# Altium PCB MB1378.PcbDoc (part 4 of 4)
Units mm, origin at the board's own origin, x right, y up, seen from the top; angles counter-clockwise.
Board outline 54.22 x 80.1 mm, 4 copper layers (Top Layer, L2-GND, L3, Bottom Layer), stack 0.771 mm thick; 206 components, 159 nets, 727 pads, 330 vias.
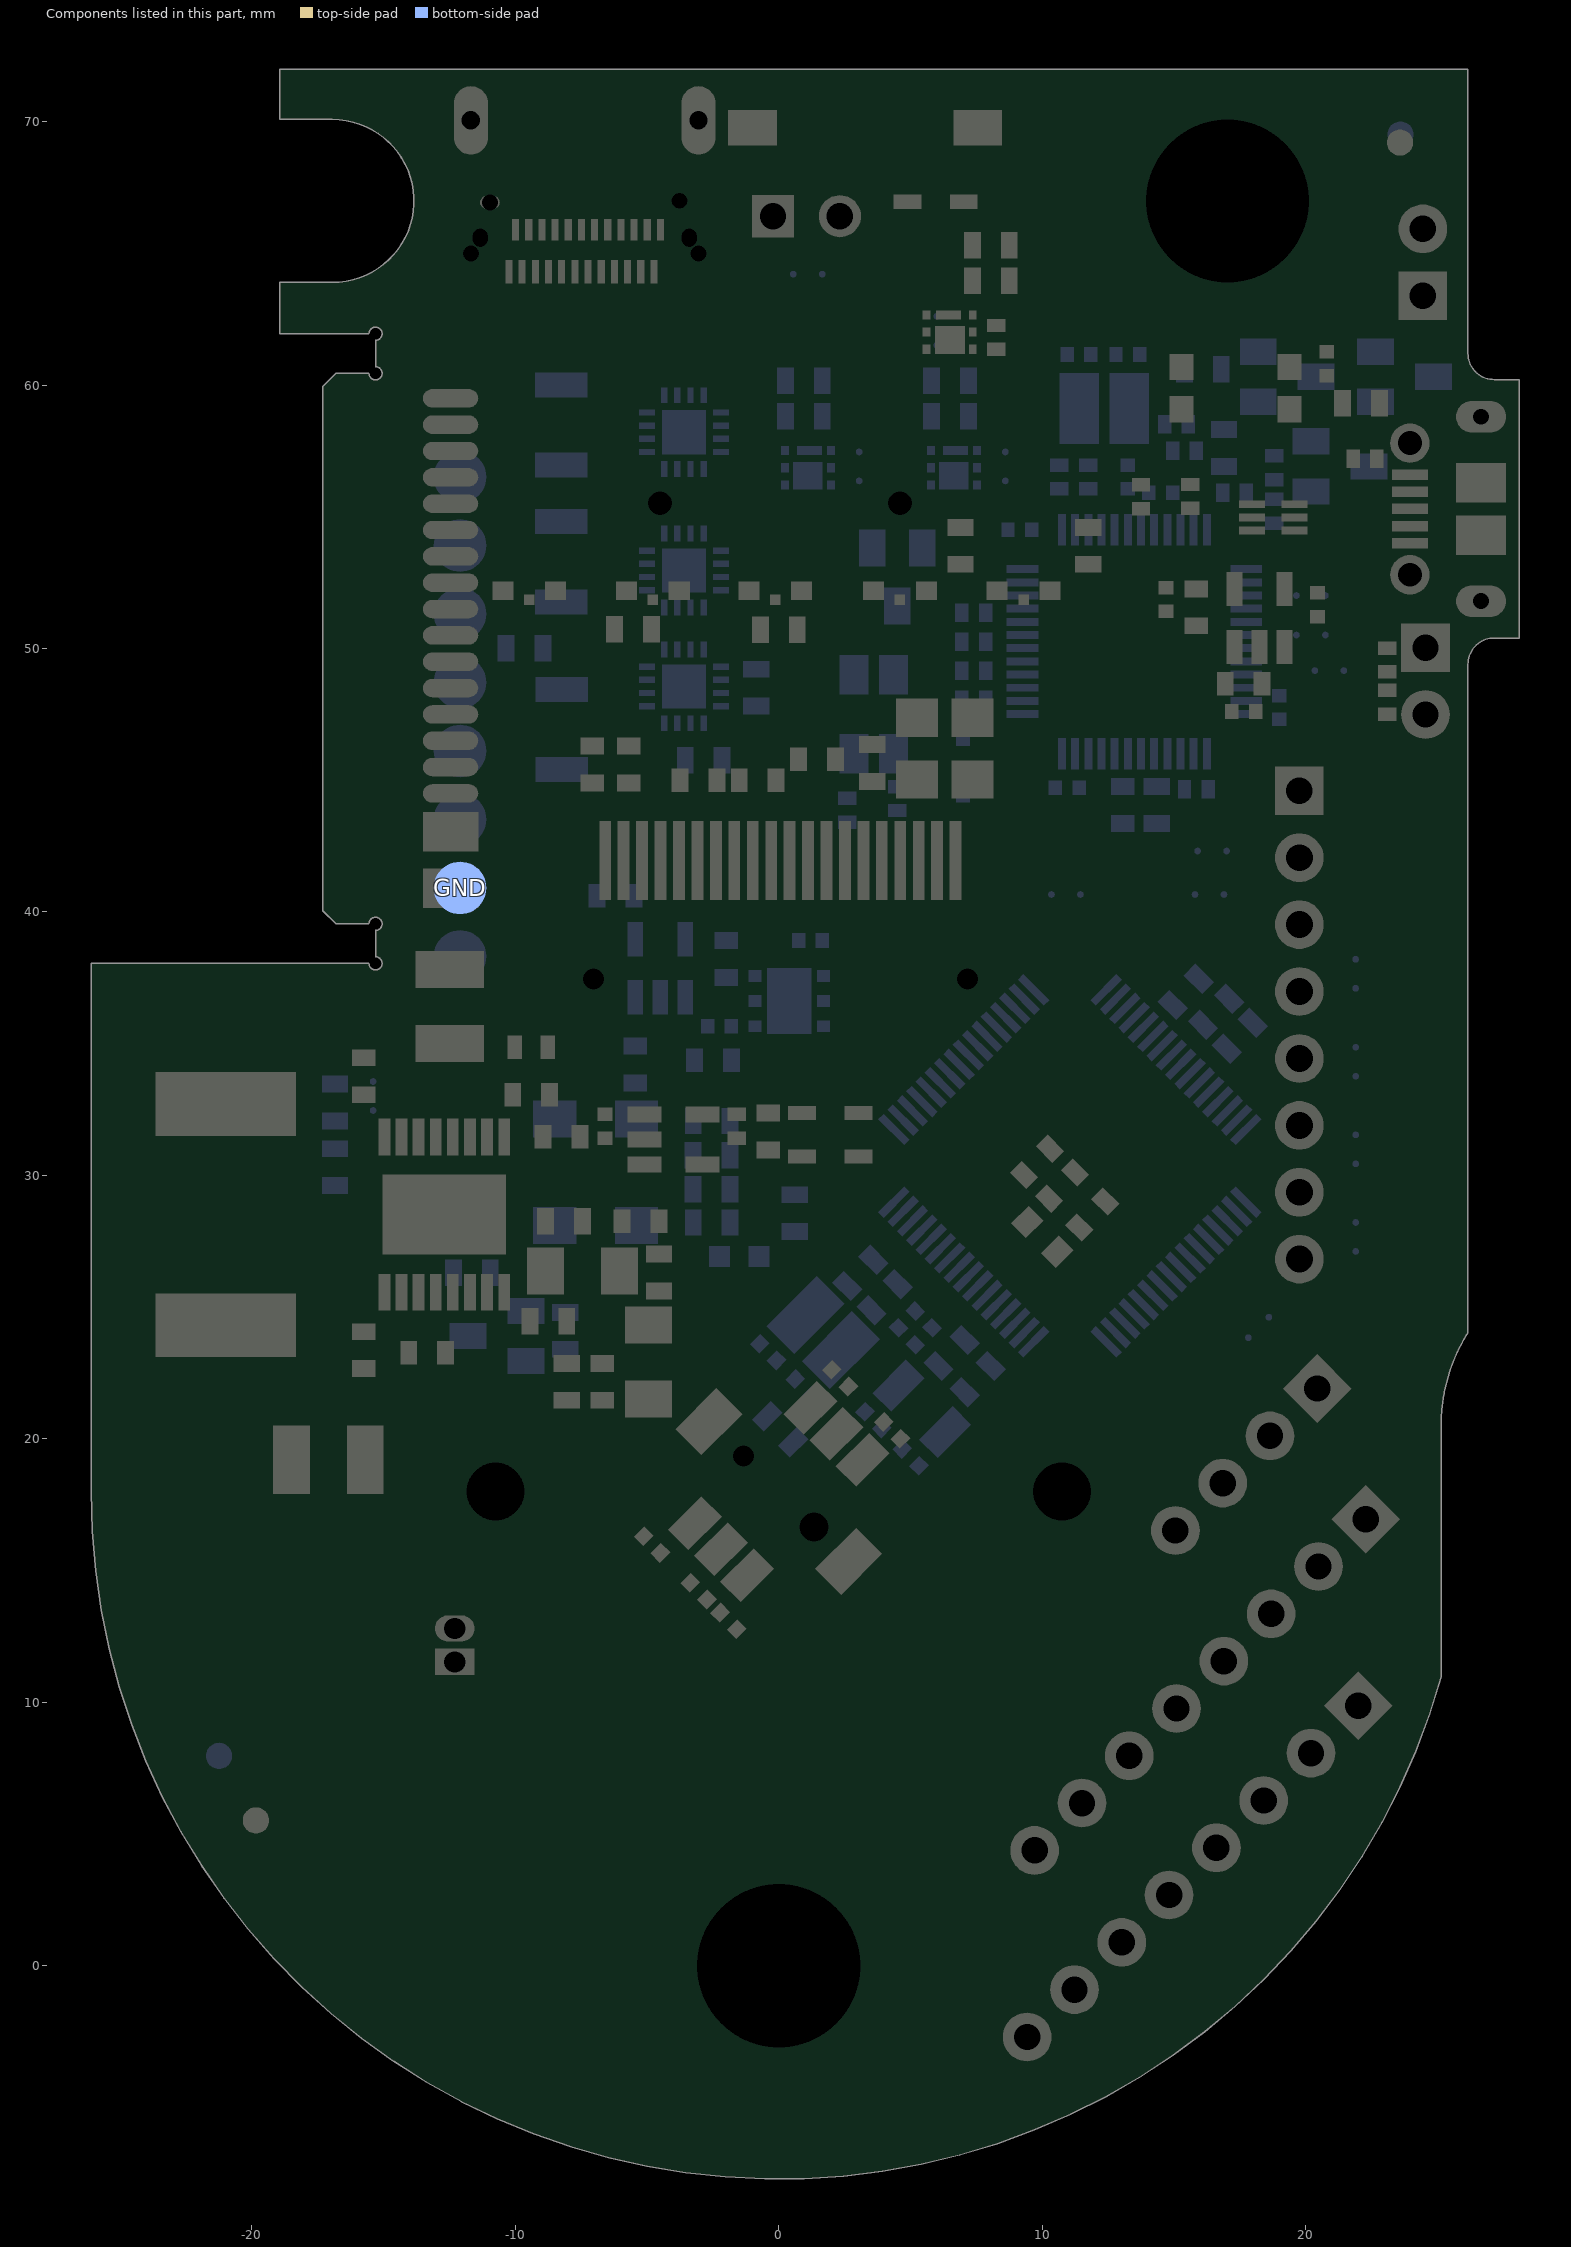
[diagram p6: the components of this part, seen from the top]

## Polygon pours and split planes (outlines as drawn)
NetC9_2 on Top Layer "L01_NETC9_2_P016" (solid, remove dead copper, pour order 16): -15.367,23.752 -15.367,24.557 -17.097,24.557 -17.097,28.352 -19.167,28.352 -24.367,28.352 -25.567,27.152 -25.567,22.202 -24.867,21.502 -17.617,21.502 -16.417,22.702 -16.417,23.552 -16.217,23.752
NetC8_2 on Top Layer "L01_NETC8_2_P017" (solid, remove dead copper, pour order 17): -15.367,33.352 -15.367,32.412 -16.731,32.412 -16.731,28.752 -19.269,28.752 -24.367,28.752 -25.567,29.952 -25.567,34.902 -24.867,35.602 -17.617,35.602 -16.417,34.402 -16.417,33.552 -16.217,33.352
GND on Top Layer "L01_GND_P018" (solid, remove dead copper, pour order 18): -26.106,26.748 -26.106,27.448 -26.106,27.798 -26.106,35.499 -26.107,35.499 -26.107,38.049 -15.557,38.049 ccw(c-15.307,38.049) -15.307,38.299 -15.307,39.299 ccw(c-15.307,39.549) -15.557,39.549 -16.807,39.549 -17.307,40.049 -17.307,59.949 -16.807,60.449 -15.557,60.449 ccw(c-15.307,60.449) -15.307,60.699 -15.307,61.699 ccw(c-15.307,61.949) -15.557,61.949 -18.942,61.949 -18.942,63.896 -16.942,63.896 ccw(c-16.942,66.99) -16.942,70.083 -18.942,70.083 -18.942,71.999 4.624,71.999 14.545,71.999 26.163,71.999 26.163,62.147 26.163,61.209 ccw(c27.163,61.209) 27.163,60.209 28.109,60.209 28.109,50.399 27.163,50.399 ccw(c27.163,49.399) 26.163,49.399 26.163,46.114 26.163,25.294 26.163,24.023 26.124,23.96 26.086,23.897 26.048,23.834 26.011,23.771 25.975,23.707 25.939,23.642 25.905,23.578 25.871,23.513 25.837,23.447 25.805,23.381 25.773,23.315 25.742,23.249 25.712,23.182 25.682,23.115 25.654,23.047 25.626,22.979 25.599,22.911 25.572,22.843 25.547,22.774 25.522,22.705 25.498,22.636 25.474,22.566 25.452,22.497 25.43,22.427 25.409,22.356 25.389,22.286 25.37,22.215 25.351,22.144 25.333,22.073 25.316,22.002 25.3,21.93 25.285,21.858 25.27,21.786 25.257,21.714 25.244,21.642 25.232,21.57 25.22,21.497 25.21,21.424 25.2,21.351 25.191,21.278 25.183,21.205 25.176,21.132 25.17,21.058 25.164,20.985 25.16,20.911 25.156,20.838 25.153,20.764 25.151,20.69 25.15,20.616 25.149,20.542 25.149,10.965 24.705,9.528 24.181,8.127 23.58,6.764 22.9,5.435 22.143,4.142 21.309,2.892 20.405,1.691 19.439,0.552 18.412,-0.528 17.323,-1.549 16.171,-2.511 14.964,-3.407 13.709,-4.23 12.416,-4.976 11.085,-5.645 9.715,-6.238 8.305,-6.754 6.865,-7.19 5.407,-7.541 3.938,-7.807 2.459,-7.988 0.97,-8.087 -0.531,-8.099 -2.035,-8.024 -3.527,-7.864 -5,-7.62 -6.455,-7.294 -7.892,-6.884 -9.31,-6.39 -10.7,-5.813 -12.052,-5.16 -13.356,-4.435 -14.615,-3.637 -15.829,-2.766 -16.996,-1.822 -18.11,-0.81 -19.162,0.261 -20.144,1.385 -21.06,2.562 -21.909,3.792 -22.69,5.077 -23.396,6.404 -24.023,7.766 -24.568,9.156 -25.032,10.574 -25.415,12.02 -25.715,13.495 -25.932,14.988 -26.062,16.49 -26.106,17.998
GND on L2-GND "L02_GND_P019" (solid, remove dead copper, pour order 19): -26.106,26.748 -26.106,27.448 -26.106,27.798 -26.106,35.499 -26.107,35.499 -26.107,38.049 -15.557,38.049 ccw(c-15.307,38.049) -15.307,38.299 -15.307,39.299 ccw(c-15.307,39.549) -15.557,39.549 -16.807,39.549 -17.307,40.049 -17.307,59.949 -16.807,60.449 -15.557,60.449 ccw(c-15.307,60.449) -15.307,60.699 -15.307,61.699 ccw(c-15.307,61.949) -15.557,61.949 -18.942,61.949 -18.942,63.896 -16.942,63.896 ccw(c-16.942,66.99) -16.942,70.083 -18.942,70.083 -18.942,71.999 4.624,71.999 14.545,71.999 26.163,71.999 26.163,62.147 26.163,61.209 ccw(c27.163,61.209) 27.163,60.209 28.109,60.209 28.109,50.399 27.163,50.399 ccw(c27.163,49.399) 26.163,49.399 26.163,46.114 26.163,25.294 26.163,24.023 26.124,23.96 26.086,23.897 26.048,23.834 26.011,23.771 25.975,23.707 25.939,23.642 25.905,23.578 25.871,23.513 25.837,23.447 25.805,23.381 25.773,23.315 25.742,23.249 25.712,23.182 25.682,23.115 25.654,23.047 25.626,22.979 25.599,22.911 25.572,22.843 25.547,22.774 25.522,22.705 25.498,22.636 25.474,22.566 25.452,22.497 25.43,22.427 25.409,22.356 25.389,22.286 25.37,22.215 25.351,22.144 25.333,22.073 25.316,22.002 25.3,21.93 25.285,21.858 25.27,21.786 25.257,21.714 25.244,21.642 25.232,21.57 25.22,21.497 25.21,21.424 25.2,21.351 25.191,21.278 25.183,21.205 25.176,21.132 25.17,21.058 25.164,20.985 25.16,20.911 25.156,20.838 25.153,20.764 25.151,20.69 25.15,20.616 25.149,20.542 25.149,10.965 24.705,9.528 24.181,8.127 23.58,6.764 22.9,5.435 22.143,4.142 21.309,2.892 20.405,1.691 19.439,0.552 18.412,-0.528 17.323,-1.549 16.171,-2.511 14.964,-3.407 13.709,-4.23 12.416,-4.976 11.085,-5.645 9.715,-6.238 8.305,-6.754 6.865,-7.19 5.407,-7.541 3.938,-7.807 2.459,-7.988 0.97,-8.087 -0.531,-8.099 -2.035,-8.024 -3.527,-7.864 -5,-7.62 -6.455,-7.294 -7.892,-6.884 -9.31,-6.39 -10.7,-5.813 -12.052,-5.16 -13.356,-4.435 -14.615,-3.637 -15.829,-2.766 -16.996,-1.822 -18.11,-0.81 -19.162,0.261 -20.144,1.385 -21.06,2.562 -21.909,3.792 -22.69,5.077 -23.396,6.404 -24.023,7.766 -24.568,9.156 -25.032,10.574 -25.415,12.02 -25.715,13.495 -25.932,14.988 -26.062,16.49 -26.106,17.998
GND on Bottom Layer "L04_GND_P020" (solid, remove dead copper, pour order 20): -26.106,26.748 -26.106,27.448 -26.106,27.798 -26.106,35.499 -26.107,35.499 -26.107,38.049 -15.557,38.049 ccw(c-15.307,38.049) -15.307,38.299 -15.307,39.299 ccw(c-15.307,39.549) -15.557,39.549 -16.807,39.549 -17.307,40.049 -17.307,59.949 -16.807,60.449 -15.557,60.449 ccw(c-15.307,60.449) -15.307,60.699 -15.307,61.699 ccw(c-15.307,61.949) -15.557,61.949 -18.942,61.949 -18.942,63.896 -16.942,63.896 ccw(c-16.942,66.99) -16.942,70.083 -18.942,70.083 -18.942,71.999 4.624,71.999 14.545,71.999 26.163,71.999 26.163,62.147 26.163,61.209 ccw(c27.163,61.209) 27.163,60.209 28.109,60.209 28.109,50.399 27.163,50.399 ccw(c27.163,49.399) 26.163,49.399 26.163,46.114 26.163,25.294 26.163,24.023 26.124,23.96 26.086,23.897 26.048,23.834 26.011,23.771 25.975,23.707 25.939,23.642 25.905,23.578 25.871,23.513 25.837,23.447 25.805,23.381 25.773,23.315 25.742,23.249 25.712,23.182 25.682,23.115 25.654,23.047 25.626,22.979 25.599,22.911 25.572,22.843 25.547,22.774 25.522,22.705 25.498,22.636 25.474,22.566 25.452,22.497 25.43,22.427 25.409,22.356 25.389,22.286 25.37,22.215 25.351,22.144 25.333,22.073 25.316,22.002 25.3,21.93 25.285,21.858 25.27,21.786 25.257,21.714 25.244,21.642 25.232,21.57 25.22,21.497 25.21,21.424 25.2,21.351 25.191,21.278 25.183,21.205 25.176,21.132 25.17,21.058 25.164,20.985 25.16,20.911 25.156,20.838 25.153,20.764 25.151,20.69 25.15,20.616 25.149,20.542 25.149,10.965 24.705,9.528 24.181,8.127 23.58,6.764 22.9,5.435 22.143,4.142 21.309,2.892 20.405,1.691 19.439,0.552 18.412,-0.528 17.323,-1.549 16.171,-2.511 14.964,-3.407 13.709,-4.23 12.416,-4.976 11.085,-5.645 9.715,-6.238 8.305,-6.754 6.865,-7.19 5.407,-7.541 3.938,-7.807 2.459,-7.988 0.97,-8.087 -0.531,-8.099 -2.035,-8.024 -3.527,-7.864 -5,-7.62 -6.455,-7.294 -7.892,-6.884 -9.31,-6.39 -10.7,-5.813 -12.052,-5.16 -13.356,-4.435 -14.615,-3.637 -15.829,-2.766 -16.996,-1.822 -18.11,-0.81 -19.162,0.261 -20.144,1.385 -21.06,2.562 -21.909,3.792 -22.69,5.077 -23.396,6.404 -24.023,7.766 -24.568,9.156 -25.032,10.574 -25.415,12.02 -25.715,13.495 -25.932,14.988 -26.062,16.49 -26.106,17.998
GND on L3 "L03_GND_P021" (solid, remove dead copper, pour order 21): -26.106,26.748 -26.106,27.448 -26.106,27.798 -26.106,35.499 -26.107,35.499 -26.107,38.049 -15.557,38.049 ccw(c-15.307,38.049) -15.307,38.299 -15.307,39.299 ccw(c-15.307,39.549) -15.557,39.549 -16.807,39.549 -17.307,40.049 -17.307,59.949 -16.807,60.449 -15.557,60.449 ccw(c-15.307,60.449) -15.307,60.699 -15.307,61.699 ccw(c-15.307,61.949) -15.557,61.949 -18.942,61.949 -18.942,63.896 -16.942,63.896 ccw(c-16.942,66.99) -16.942,70.083 -18.942,70.083 -18.942,71.999 4.624,71.999 14.545,71.999 26.163,71.999 26.163,62.147 26.163,61.209 ccw(c27.163,61.209) 27.163,60.209 28.109,60.209 28.109,50.399 27.163,50.399 ccw(c27.163,49.399) 26.163,49.399 26.163,46.114 26.163,25.294 26.163,24.023 26.124,23.96 26.086,23.897 26.048,23.834 26.011,23.771 25.975,23.707 25.939,23.642 25.905,23.578 25.871,23.513 25.837,23.447 25.805,23.381 25.773,23.315 25.742,23.249 25.712,23.182 25.682,23.115 25.654,23.047 25.626,22.979 25.599,22.911 25.572,22.843 25.547,22.774 25.522,22.705 25.498,22.636 25.474,22.566 25.452,22.497 25.43,22.427 25.409,22.356 25.389,22.286 25.37,22.215 25.351,22.144 25.333,22.073 25.316,22.002 25.3,21.93 25.285,21.858 25.27,21.786 25.257,21.714 25.244,21.642 25.232,21.57 25.22,21.497 25.21,21.424 25.2,21.351 25.191,21.278 25.183,21.205 25.176,21.132 25.17,21.058 25.164,20.985 25.16,20.911 25.156,20.838 25.153,20.764 25.151,20.69 25.15,20.616 25.149,20.542 25.149,10.965 24.705,9.528 24.181,8.127 23.58,6.764 22.9,5.435 22.143,4.142 21.309,2.892 20.405,1.691 19.439,0.552 18.412,-0.528 17.323,-1.549 16.171,-2.511 14.964,-3.407 13.709,-4.23 12.416,-4.976 11.085,-5.645 9.715,-6.238 8.305,-6.754 6.865,-7.19 5.407,-7.541 3.938,-7.807 2.459,-7.988 0.97,-8.087 -0.531,-8.099 -2.035,-8.024 -3.527,-7.864 -5,-7.62 -6.455,-7.294 -7.892,-6.884 -9.31,-6.39 -10.7,-5.813 -12.052,-5.16 -13.356,-4.435 -14.615,-3.637 -15.829,-2.766 -16.996,-1.822 -18.11,-0.81 -19.162,0.261 -20.144,1.385 -21.06,2.562 -21.909,3.792 -22.69,5.077 -23.396,6.404 -24.023,7.766 -24.568,9.156 -25.032,10.574 -25.415,12.02 -25.715,13.495 -25.932,14.988 -26.062,16.49 -26.106,17.998

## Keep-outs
Keep-Out Layer:
  lines w0.4: -26.107,17.649 -26.107,38.049 -15.557,38.049 ccw(c-15.307,38.049) -15.307,38.299 -15.307,39.299 ccw(c-15.307,39.549) -15.557,39.549 -16.807,39.549 -17.307,40.049 -17.307,59.949 -16.807,60.449 -15.557,60.449 ccw(c-15.307,60.449) -15.307,60.699 -15.307,61.67 -15.307,61.699 ccw(c-15.307,61.949) -15.557,61.949 -18.942,61.949 -18.942,63.896 -16.942,63.896 ccw(c-16.942,66.99) -16.942,70.083 -18.942,70.083 -18.942,71.999 26.163,71.999 26.163,61.209 ccw(c27.163,61.209) 27.163,60.209 28.109,60.209 28.109,50.399 27.163,50.399 ccw(c27.163,49.399) 26.163,49.399 26.163,24.023 26.124,23.96 26.086,23.897 26.048,23.834 26.011,23.771 25.975,23.707 25.939,23.642 25.905,23.578 25.871,23.513 25.837,23.447 25.805,23.381 25.773,23.315 25.742,23.249 25.712,23.182 25.682,23.115 25.654,23.047 25.626,22.979 25.599,22.911 25.572,22.843 25.547,22.774 25.522,22.705 25.498,22.636 25.474,22.566 25.452,22.497 25.43,22.427 25.409,22.356 25.389,22.286 25.37,22.215 25.351,22.144 25.333,22.073 25.316,22.002 25.3,21.93 25.285,21.858 25.27,21.786 25.257,21.714 25.244,21.642 25.232,21.57 25.22,21.497 25.21,21.424 25.2,21.351 25.191,21.278 25.183,21.205 25.176,21.132 25.17,21.058 25.164,20.985 25.16,20.911 25.156,20.838 25.153,20.764 25.151,20.69 25.15,20.616 25.149,20.542 25.149,10.965 24.705,9.528 24.181,8.127 23.58,6.764 22.9,5.435 22.143,4.142 21.309,2.892 20.405,1.691 19.439,0.552 18.412,-0.528 17.323,-1.549 16.171,-2.511 14.964,-3.407 13.709,-4.23 12.416,-4.976 11.085,-5.645 9.715,-6.238 8.305,-6.754 6.865,-7.19 5.407,-7.541 3.938,-7.807 2.459,-7.988 0.97,-8.087 -0.531,-8.099 -2.035,-8.024 -3.527,-7.864 -5,-7.62 -6.455,-7.294 -7.892,-6.884 -9.31,-6.39 -10.7,-5.813 -12.052,-5.16 -13.356,-4.435 -14.615,-3.637 -15.829,-2.766 -16.996,-1.822 -18.11,-0.81 -19.162,0.261 -20.144,1.385 -21.06,2.562 -21.909,3.792 -22.69,5.077 -23.396,6.404 -24.023,7.766 -24.568,9.156 -25.032,10.574 -25.415,12.02 -25.715,13.495 -25.932,14.988 ; -26.106,17.898 -26.062,16.39 -25.932,14.888

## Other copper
Top Layer:
  region net 5V_SMPS_VBUS: -13.747,22.662 -13.747,20.962 -13.747,17.998 -15.829,17.998 -15.829,20.542 -14.347,20.542 -14.347,22.662
  region net VBUS_P: -9.747,35.912 -14.147,35.912 -14.597,35.462 -14.597,33.512 -13.897,32.812 -13.897,31.512 -13.447,31.512 -13.447,34.112 -13.297,34.262 -11.447,34.262 -11.297,34.112 -11.297,30.762 -10.847,30.762 -10.847,32.362 -9.747,32.362
  pour cut-out: -10.565,63.699 -9.965,63.699 -9.965,62.599 -10.565,62.599
  text ".Layer_Name" at 143.208,-57.639 h4
  text ".GTL" at 207.158,-57.683 h4
  text "03" at 210.038,-63.733 h4.5
L2-GND:
  text ".Layer_Name" at 143.208,-57.649 h4
  text ".G1" at 207.158,-57.683 h4
  text "04" at 210.038,-63.733 h4.5
L3:
  text ".Layer_Name" at 143.208,-57.649 h4
  text ".G2" at 207.158,-57.683 h4
  text "05" at 210.038,-63.733 h4.5
Bottom Layer:
  text ".Layer_Name" at 143.208,-57.639 h4
  text ".GBL" at 207.158,-57.683 h4
  text "06" at 210.038,-63.733 h4.5

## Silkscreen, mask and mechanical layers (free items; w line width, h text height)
Top Overlay:
  text "RESET" at 15.72,57.46 h1.2
  text "ST-LINK" at 23.01,52.53 h1.2 r90
  text "VDD" at 15.6,44.1 h1.5
  text "5V_SMPS / _VBUS" at 10.5,40.25 h1.5
  text "GND" at 15.6,39 h1.5
  text "PB2" at 15.6,36.5 h1.5
  text "PD0" at 15.6,33.9 h1.5
  text "PD2" at 15.6,31.5 h1.5
  text "PB8" at 15.6,28.9 h1.5
  text "PB9" at 15.6,26.4 h1.5
  text "CN8" at 21.087,18.597 h1.5
  text "PB0" at 18.3,16.95 h1.5
  text "PA15" at 16.103,15.162 h1.5
  text "PB1" at 14.603,13.362 h1.5
  text "PB3" at 13.253,11.562 h1.5
  text "CN9" at 20.803,11.512 h1.5
  text "PB4" at 11.403,9.812 h1.5
  text "VDD" at 17.603,9.812 h1.5
  text "PD6" at 16.303,8.112 h1.5
  text "PB5" at 9.453,7.962 h1.5
  text "PC9" at 14.603,6.412 h1.5
  text "PB14" at 7.103,6.162 h1.5
  text "PC13" at 12.403,4.512 h1.5
  text "GND" at 5.453,4.312 h1.5
  text "PD1" at 11.103,2.712 h1.5
  text "PD3" at 9.168,0.878 h1.5
  text "PD4" at 7.303,-0.888 h1.5
  text "5V" at 6.303,-2.788 h1.5
  text ".GTO" at 207.158,-57.583 h4
  text "Silkscreen Top" at 143.358,-57.683 h4
  text "01" at 210.038,-63.733 h4.5
Bottom Overlay:
  region: 1.564,71.607 1.583,71.603 3.143,71.603 3.136,67.972 2.763,68.249 2.763,69.583 2.068,69.583 cw(c0.198,69.796) -1.329,68.697 -1.006,68.937 ccw(c0.184,69.795) -1.012,70.644 -1.302,70.906 cw(c0.205,69.792) 2.068,69.99 2.763,69.99 2.763,71.211 1.883,71.211
  region: -0.702,69.162 -0.37,69.408 ccw(c0.184,69.79) -0.37,70.173 -0.702,70.418 cw(c0.184,69.79)
  lines w0.2: 20.49,35.315 20.49,35.605 21.115,36.23 ; 20.625,32.68 20.633,32.69 21.236,32.759 21.235,32.76 22.845,32.765 ; 20.735,26.245 21.401,25.764 ; 20.92,29.516 22.785,29.54 ; 22.18,25.76 21.401,25.764 ; 23,36.235 21.115,36.23 ; 21.115,36.23 21.115,36.23 ; 21.401,25.764 21.401,25.764 ; -24.102,21.668 -24.102,36.668 -19.102,36.668 -19.102,21.668 -24.102,21.668 ; -19,1 -4,1 -4,6 -19,6 -19,1
  text "IDD" at 6.37,63.85 h1.2
  text "STLK_RST" at 20.66,63.55 h1.2 r270
  text "VDD" at 22.19,45.77 h1.2
  text "STLK" at 25.71,44.01 h1.2
  text "5V_SMPS / _VBUS" at 27.5,40.455 h1.2
  text "GND" at 24.46,39.755 h1.2
  text "PB2" at 18.46,38.145 h1.2
  text "PD0" at 25.215,35.825 h1.2
  text "PD2" at 25.21,32.54 h1.2
  text "PB8" at 25.125,29.155 h1.2
  text "PB9" at 24.2,25.47 h1.2
  text "3V3_STLK" at 18.402,21.7 h1.5
  text "SWCLK" at 16.95,20.248 h1.5
  text "PB0" at 23.85,19.25 h1.5
  text "GND" at 15.22,18.775 h1.5
  text "PA15" at 20.55,17.55 h1.5 r45
  text "SWDIO" at 13.5,15.1 h1.5
  text "PB1" at 16.95,13.65 h1.5
  text "PB3" at 15.5,12.3 h1.5
  text "VDD" at 24.7,11.95 h1.5
  text "PB4" at 13.8,10.6 h1.5
  text "PD6" at 19.7,9.9 h1.5 r45
  text "TARGET_RST" at -10.45,9.77 h1.2
  text "PB5" at 11.8,8.8 h1.5
  text "MB1378C" at -6,7 h2.5
  text "PB14" at 9.9,6.85 h1.5
  text "GND" at 8.3,5.2 h1.5
  text "PC9" at 22.15,4.7 h1.5
  text "G" at 4.39,3.95 h10
  text "PC13" at 20.85,2.7 h1.5
  text "PD1" at 18.7,1.2 h1.5
  text "PD3" at 16.95,-0.55 h1.5
  text "PD4" at 15.05,-2.6 h1.5
  text "5V" at 12.35,-4.35 h1.5
  text ".GBO" at 207.158,-57.483 h4
  text "Silkscreen Bottom" at 143.358,-57.583 h4
  text "08" at 210.038,-63.733 h4.5
Top Paste:
  text ".Layer_Name" at 143.208,-57.639 h4
  text ".GTP" at 207.158,-57.683 h4
  text "11" at 210.038,-63.781 h4.5
Bottom Paste:
  text ".Layer_Name" at 143.208,-57.639 h4
  text ".GBP" at 207.158,-57.683 h4
  text "12" at 210.038,-63.733 h4.5
Top Solder:
  text ".Layer_Name" at 143.208,-57.683 h4
  text ".GTS" at 207.158,-57.683 h4
  text "02" at 210.038,-63.733 h4.5
Bottom Solder:
  text ".Layer_Name" at 143.208,-57.683 h4
  text ".GBS" at 207.158,-57.683 h4
  text "07" at 210.038,-63.733 h4.5
M1-Board Shape:
  circle w0.013: c10.756,17.999 r1.1
  circle w0.013: c17.036,66.99 r3.093
  circle w0.013: c-10.756,17.999 r1.1
  circle w0.013: c0,0 r3.093
  lines w0.013: -26.106,17.898 -26.106,18.248 -26.106,18.598 -26.106,18.948 -26.106,19.298 -26.106,19.648 -26.106,19.998 -26.106,20.348
  lines w0.2: -26.107,17.649 -26.107,38.049 -15.557,38.049 ccw(c-15.307,38.049) -15.307,38.299 -15.307,39.299 ccw(c-15.307,39.549) -15.557,39.549 -16.807,39.549 -17.307,40.049 -17.307,59.949 -16.807,60.449 -15.557,60.449 ccw(c-15.307,60.449) -15.307,60.699 -15.307,61.67 -15.307,61.699 ccw(c-15.307,61.949) -15.557,61.949 -18.942,61.949 -18.942,63.896 -16.942,63.896 ccw(c-16.942,66.99) -16.942,70.083 -18.942,70.083 -18.942,71.999 -16.942,71.999 -14.545,71.999 4.624,71.999 14.545,71.999 19.526,71.999 26.163,71.999 26.163,67.999 26.163,62.147 26.163,61.209 ccw(c27.163,61.209) 27.163,60.209 28.109,60.209 28.109,50.399 27.163,50.399 ccw(c27.163,49.399) 26.163,49.399 26.163,46.114 26.163,25.294 26.163,24.023 26.124,23.96 26.086,23.897 26.048,23.834 26.011,23.771 25.975,23.707 25.939,23.642 25.905,23.578 25.871,23.513 25.837,23.447 25.805,23.381 25.773,23.315 25.742,23.249 25.712,23.182 25.682,23.115 25.654,23.047 25.626,22.979 25.599,22.911 25.572,22.843 25.547,22.774 25.522,22.705 25.498,22.636 25.474,22.566 25.452,22.497 25.43,22.427 25.409,22.356 25.389,22.286 25.37,22.215 25.351,22.144 25.333,22.073 25.316,22.002 25.3,21.93 25.285,21.858 25.27,21.786 25.257,21.714 25.244,21.642 25.232,21.57 25.22,21.497 25.21,21.424 25.2,21.351 25.191,21.278 25.183,21.205 25.176,21.132 25.17,21.058 25.164,20.985 25.16,20.911 25.156,20.838 25.153,20.764 25.151,20.69 25.15,20.616 25.149,20.542 25.149,10.965 24.705,9.528 24.181,8.127 23.58,6.764 22.9,5.435 22.143,4.142 21.309,2.892 20.405,1.691 19.439,0.552 18.412,-0.528 17.323,-1.549 16.171,-2.511 14.964,-3.407 13.709,-4.23 12.416,-4.976 11.085,-5.645 9.715,-6.238 8.305,-6.754 6.865,-7.19 5.407,-7.541 3.938,-7.807 2.459,-7.988 0.97,-8.087 -0.531,-8.099 -2.035,-8.024 -3.527,-7.864 -5,-7.62 -6.455,-7.294 -7.892,-6.884 -9.31,-6.39 -10.7,-5.813 -12.052,-5.16 -13.356,-4.435 -14.615,-3.637 -15.829,-2.766 -16.996,-1.822 -18.11,-0.81 -19.162,0.261 -20.144,1.385 -21.06,2.562 -21.909,3.792 -22.69,5.077 -23.396,6.404 -24.023,7.766 -24.568,9.156 -25.032,10.574 -25.415,12.02 -25.715,13.495 -25.932,14.988 ; -26.106,17.898 -26.062,16.39 -25.932,14.888
M2-Board Dimensions:
  text "Mechanical Drawing" at 143.208,-57.683 h4
  text "10" at 210.038,-63.733 h4.5
M5-Top Constraints:
  drawing of 14713 lines, arcs and shapes, not listed
M14-Top Assembly:
  text "'.Layer_Name'" at 143.358,-57.583 h4
  text "13" at 210.038,-63.781 h4.5
M15-Bottom Assembly:
  text ".Layer_Name" at 22.508,-57.639 h4
  text "14" at -44.321,-63.733 h4.5
Drill Drawing:
  lines w0.254: 54.384,74.001 56.685,74.001 56.685,76.302 54.384,76.302 54.384,74.001 ; 54.384,117.722 56.685,117.722 55.535,115.421 54.384,117.722
  lines w0.381: 52.349,36.206 216.578,36.206 ; 52.349,119.045 216.578,119.045 ; 52.549,10.823 159.583,10.823 ; 52.549,16 159.583,16 ; 65.654,31.029 65.654,124.223 ; 65.854,5.646 65.854,21.178 ; 76.827,5.646 76.827,21.178 ; 77.842,31.029 77.842,124.223 ; 97.177,5.646 97.177,21.178 ; 100.691,31.029 100.691,124.223 ; 107.494,5.646 107.494,21.178 ; 111.008,31.029 111.008,124.223 ; 122.513,5.646 122.513,21.178 ; 126.027,31.029 126.027,124.223 ; 145.723,5.646 145.723,21.178 ; 154.494,31.029 154.494,124.223 ; 166.801,31.029 166.801,124.223 ; 188.424,31.029 188.424,124.223 ; 52.349,31.029 216.578,31.029 216.578,124.223 52.349,124.223 52.349,31.029 ; 52.549,5.646 159.583,5.646 159.583,21.178 52.549,21.178 52.549,5.646
  text "Symbol" at 55.455,120.598 h3
  text "Count" at 67.207,120.598 h3
  text "Hole Size" at 79.396,120.598 h3
  text "Plated" at 102.245,120.598 h3
  text "Hole Type" at 112.561,120.598 h3
  text "Drill Layer Pair" at 127.58,120.598 h3
  text "Via/Pad" at 156.047,120.598 h3
  text "Hole Length" at 168.354,120.598 h3
  text "Routed Path Length" at 189.977,120.598 h3
  text "308" at 67.207,115.421 h2.5
  text "0,15mm (5,91mil)" at 79.396,115.421 h2.5
  text "PTH" at 102.245,115.421 h2.5
  text "Round" at 112.561,115.421 h2.5
  text "Top Layer - Bottom Layer" at 127.58,115.421 h2.5
  text "Via" at 156.047,115.421 h2.5
  text "-" at 168.354,115.421 h2.5
  text "-" at 189.977,115.421 h2.5
  text "1" at 67.207,110.243 h2.5
  text "0,60mm (23,62mil)" at 79.396,110.243 h2.5
  text "NPTH" at 102.245,110.243 h2.5
  text "Round" at 112.561,110.243 h2.5
  text "Top Layer - Bottom Layer" at 127.58,110.243 h2.5
  text "Pad" at 156.047,110.243 h2.5
  text "-" at 168.354,110.243 h2.5
  text "-" at 189.977,110.243 h2.5
  text "E" at 54.514,109.99 h2.3
  text "1" at 67.207,105.066 h2.5
  text "0,60mm (23,62mil)" at 79.396,105.066 h2.5
  text "NPTH" at 102.245,105.066 h2.5
  text "Slot" at 112.561,105.066 h2.5
  text "Top Layer - Bottom Layer" at 127.58,105.066 h2.5
  text "Pad" at 156.047,105.066 h2.5
  text "0,85mm (33,47mil)" at 168.354,105.066 h2.5
  text "0,25mm (9,84mil)" at 189.977,105.066 h2.5
  text "F" at 54.514,104.812 h2.3
  text "4" at 67.207,99.889 h2.5
  text "0,60mm (23,62mil)" at 79.396,99.889 h2.5
  text "PTH" at 102.245,99.889 h2.5
  text "Slot" at 112.561,99.889 h2.5
  text "Top Layer - Bottom Layer" at 127.58,99.889 h2.5
  text "Pad" at 156.047,99.889 h2.5
  text "1,20mm (47,24mil)" at 168.354,99.889 h2.5
  text "0,60mm (23,62mil)" at 189.977,99.889 h2.5
  text "D" at 54.514,99.635 h2.3
  text "2" at 67.207,94.711 h2.5
  text "0,60mm (23,62mil)" at 79.396,94.711 h2.5
  text "PTH" at 102.245,94.711 h2.5
  text "Slot" at 112.561,94.711 h2.5
  text "Top Layer - Bottom Layer" at 127.58,94.711 h2.5
  text "Pad" at 156.047,94.711 h2.5
  text "1,30mm (51,18mil)" at 168.354,94.711 h2.5
  text "0,70mm (27,56mil)" at 189.977,94.711 h2.5
  text "C" at 54.514,94.458 h2.3
  text "2" at 67.207,89.534 h2.5
  text "0,60mm (23,62mil)" at 79.396,89.534 h2.5
  text "PTH" at 102.245,89.534 h2.5
  text "Slot" at 112.561,89.534 h2.5
  text "Top Layer - Bottom Layer" at 127.58,89.534 h2.5
  text "Pad" at 156.047,89.534 h2.5
  text "1,90mm (74,80mil)" at 168.354,89.534 h2.5
  text "1,30mm (51,18mil)" at 189.977,89.534 h2.5
  text "G" at 54.514,89.28 h2.3
  text "2" at 67.207,84.356 h2.5
  text "0,70mm (27,56mil)" at 79.396,84.356 h2.5
  text "PTH" at 102.245,84.356 h2.5
  text "Slot" at 112.561,84.356 h2.5
  text "Top Layer - Bottom Layer" at 127.58,84.356 h2.5
  text "Pad" at 156.047,84.356 h2.5
  text "2,00mm (78,74mil)" at 168.354,84.356 h2.5
  text "1,30mm (51,18mil)" at 189.977,84.356 h2.5
  text "H" at 54.514,84.103 h2.3
  text "3" at 67.207,79.179 h2.5
  text "0,80mm (31,50mil)" at 79.396,79.179 h2.5
  text "NPTH" at 102.245,79.179 h2.5
  text "Round" at 112.561,79.179 h2.5
  text "Top Layer - Bottom Layer" at 127.58,79.179 h2.5
  text "Pad" at 156.047,79.179 h2.5
  text "-" at 168.354,79.179 h2.5
  text "-" at 189.977,79.179 h2.5
  text "I" at 54.897,78.925 h2.3
  text "2" at 67.207,74.001 h2.5
  text "0,80mm (31,50mil)" at 79.396,74.001 h2.5
  text "PTH" at 102.245,74.001 h2.5
  text "Round" at 112.561,74.001 h2.5
  text "Top Layer - Bottom Layer" at 127.58,74.001 h2.5
  text "Pad" at 156.047,74.001 h2.5
  text "-" at 168.354,74.001 h2.5
  text "-" at 189.977,74.001 h2.5
  text "2" at 67.207,68.824 h2.5
  text "0,90mm (35,43mil)" at 79.396,68.824 h2.5
  text "NPTH" at 102.245,68.824 h2.5
  text "Round" at 112.561,68.824 h2.5
  text "Top Layer - Bottom Layer" at 127.58,68.824 h2.5
  text "Pad" at 156.047,68.824 h2.5
  text "-" at 168.354,68.824 h2.5
  text "-" at 189.977,68.824 h2.5
  text "K" at 54.514,68.57 h2.3
  text "2" at 67.207,63.647 h2.5
  text "0,90mm (35,43mil)" at 79.396,63.647 h2.5
  text "PTH" at 102.245,63.647 h2.5
  text "Round" at 112.561,63.647 h2.5
  text "Top Layer - Bottom Layer" at 127.58,63.647 h2.5
  text "Pad" at 156.047,63.647 h2.5
  text "-" at 168.354,63.647 h2.5
  text "-" at 189.977,63.647 h2.5
  text "J" at 54.514,63.393 h2.3
  text "27" at 67.207,58.469 h2.5
  text "1,00mm (39,37mil)" at 79.396,58.469 h2.5
  text "PTH" at 102.245,58.469 h2.5
  text "Round" at 112.561,58.469 h2.5
  text "Top Layer - Bottom Layer" at 127.58,58.469 h2.5
  text "Pad" at 156.047,58.469 h2.5
  text "-" at 168.354,58.469 h2.5
  text "-" at 189.977,58.469 h2.5
  text "L" at 54.514,58.215 h2.3
  text "7" at 67.207,53.292 h2.5
  text "1,02mm (40,16mil)" at 79.396,53.292 h2.5
  text "PTH" at 102.245,53.292 h2.5
  text "Round" at 112.561,53.292 h2.5
  text "Top Layer - Bottom Layer" at 127.58,53.292 h2.5
  text "Pad" at 156.047,53.292 h2.5
  text "-" at 168.354,53.292 h2.5
  text "-" at 189.977,53.292 h2.5
  text "M" at 54.514,53.038 h2.3
  text "1" at 67.207,48.114 h2.5
  text "1,10mm (43,31mil)" at 79.396,48.114 h2.5
  text "NPTH" at 102.245,48.114 h2.5
  text "Round" at 112.561,48.114 h2.5
  text "Top Layer - Bottom Layer" at 127.58,48.114 h2.5
  text "Pad" at 156.047,48.114 h2.5
  text "-" at 168.354,48.114 h2.5
  text "-" at 189.977,48.114 h2.5
  text "N" at 54.514,47.861 h2.3
  text "2" at 67.207,42.937 h2.5
  text "2,20mm (86,61mil)" at 79.396,42.937 h2.5
  text "NPTH" at 102.245,42.937 h2.5
  text "Round" at 112.561,42.937 h2.5
  text "Top Layer - Bottom Layer" at 127.58,42.937 h2.5
  text "Pad" at 156.047,42.937 h2.5
  text "-" at 168.354,42.937 h2.5
  text "-" at 189.977,42.937 h2.5
  text "O" at 54.514,42.683 h2.3
  text "2" at 67.207,37.759 h2.5
  text "6,20mm (244,10mil)" at 79.396,37.759 h2.5
  text "NPTH" at 102.245,37.759 h2.5
  text "Round" at 112.561,37.759 h2.5
  text "Top Layer - Bottom Layer" at 127.58,37.759 h2.5
  text "Pad" at 156.047,37.759 h2.5
  text "-" at 168.354,37.759 h2.5
  text "-" at 189.977,37.759 h2.5
  text "P" at 54.514,37.506 h2.3
  text "368 Total" at 67.207,32.582 h2.5
  text "Slot definitions :" at 55.455,28.958 h2.5
  text "Routed Path Length" at 72.517,28.958 h2.5
  text "= Calculated from tool start centre position to tool end centre position." at 93.653,28.958 h2.5
  text "Hole Length" at 72.517,26.887 h2.5
  text "= Routed Path Length + Tool Size = Slot length as defined in the PCB layout" at 85.806,26.887 h2.5
  text "Symbol" at 55.655,17.554 h3
  text "Count" at 67.407,17.554 h3
  text "Hole Size" at 78.381,17.554 h3
  text "Plated" at 98.731,17.554 h3
  text "Hole Type" at 109.047,17.554 h3
  text "Drill Layer Pair" at 124.066,17.554 h3
  text "Via/Pad" at 147.276,17.554 h3
  text "22" at 67.407,12.376 h2.5
  text "0,10mm (3,94mil)" at 78.381,12.376 h2.5
  text "PTH" at 98.731,12.376 h2.5
  text "Round" at 109.047,12.376 h2.5
  text "Top Layer - L2-GND" at 124.066,12.376 h2.5
  text "Via" at 147.276,12.376 h2.5
  text "A" at 54.714,12.123 h2.3
  text "22 Total" at 67.407,7.199 h2.5
  text "Drill Drawing" at 143.208,-57.639 h4
  text "09" at 210.038,-63.733 h4.5
M20-Top Title Box:
  circle w0.254: c97.234,-56.907 r1.3
  region: 96.759,-49.671 81.232,-49.671 80.538,-51.446 79.327,-52.671 77.93,-50.811 77.93,-49.16 79.073,-47.763 80.509,-47.385 96.759,-47.385
  region: 82.756,-58 72,-58 72.993,-55.507 80.851,-55.507 81.3,-54.748 83.508,-57.296
  lines w0.2: -60.642,-19.733 -55.642,-19.733 ; -60.642,30.267 -50.642,30.267 ; -60.642,80.267 -55.642,80.267 ; -17.142,-69.733 -17.142,-64.733 ; -17.142,125.267 -17.142,130.267 ; 32.858,-69.733 32.858,-64.733 ; 32.858,125.267 32.858,130.267 ; 58.358,-64.733 58.358,-34.733 221.358,-34.733 ; 58.358,-59.733 221.358,-59.733 ; 58.358,-42.733 221.358,-42.733 ; 58.358,-39.276 221.358,-39.276 ; 68.858,-42.733 68.858,-34.733 ; 82.858,-69.733 82.858,-64.733 ; 82.858,120.267 82.858,130.267 ; 96.858,-42.733 96.858,-34.733 ; 111.358,-59.733 111.358,-42.733 ; 111.408,-50.733 221.358,-50.733 ; 132.858,-69.733 132.858,-64.733 ; 132.858,125.267 132.858,130.267 ; 141.358,-59.733 141.358,-50.733 ; 151.358,-42.647 151.358,-34.733 ; 171.358,-42.733 171.358,-34.733 ; 182.858,-69.733 182.858,-64.733 ; 182.858,125.267 182.858,130.267 ; 188.358,-42.647 188.358,-34.733 ; 201.358,-64.733 201.358,-59.733 ; 203.358,-42.647 203.358,-34.733 ; 209.258,-64.733 209.258,-59.733 ; 221.358,-19.733 226.358,-19.733 ; 221.358,5.267 221.358,-64.733 ; 221.358,-64.733 221.358,125.267 -55.642,125.267 -55.642,-64.733 221.358,-64.733 ; -60.642,-69.733 226.358,-69.733 226.358,130.267 -60.642,130.267 -60.642,-69.733 ; 216.358,30.267 226.358,30.267 216.358,30.267 ; 221.358,80.267 226.358,80.267 221.358,80.267
  lines w0.254: 72.993,-55.507 81.785,-55.507 78.719,-51.969 cw(c80.523,-50.025) 80.763,-47.385 97.527,-47.385 96.765,-49.671 ; 76.307,-47.137 cw(c78.733,-48.108) 78.97,-45.505 ; 76.346,-47.105 72,-58 91.323,-58 ccw(c91.571,-55.266) 94.121,-56.285 ; 78.086,-51.04 83.508,-57.296 ; 78.34,-51.04 83.645,-57.161 ; 78.34,-50.786 83.645,-56.907 ; 78.438,-49.671 91.431,-49.671 ; 78.467,-50.659 83.772,-56.78 ; 78.594,-50.532 83.899,-56.653 ; 78.721,-50.405 84.026,-56.526 ; 78.848,-50.278 84.153,-56.399 ; 78.903,-48.325 84.208,-54.446 ; 78.971,-45.506 98.421,-45.506 94.121,-56.283 ; 78.975,-50.151 84.226,-56.209 ; 78.975,-49.897 84.28,-56.018 ; 78.975,-49.643 84.28,-55.764 ; 78.975,-48.754 84.28,-54.875 ; 79.102,-49.516 84.407,-55.637 ; 79.102,-49.135 84.407,-55.256 ; 80.474,-55.521 ccw(c80.579,-54.985) 80.876,-54.528 ; 81.56,-49.657 ccw(c81.534,-50.224) 81.204,-50.687 83.569,-53.415 cw(c81.765,-55.359) 82.498,-57.908 ; 87.842,-57.796 90.731,-49.417 ; 88.064,-57.746 90.933,-49.425 ; 88.191,-57.746 91.06,-49.425 ; 88.445,-57.746 91.314,-49.425 ; 88.699,-57.746 91.568,-49.425 ; 88.953,-57.746 91.822,-49.425 ; 89.207,-57.746 92.076,-49.425 ; 89.461,-57.746 92.33,-49.425 ; 89.715,-57.746 92.584,-49.425 ; 89.969,-57.746 92.838,-49.425 ; 90.178,-57.796 93.067,-49.417 ; 93.067,-49.671 96.759,-49.671 ; 96.091,-49.668 96.853,-47.382 ; 96.257,-49.671 97.019,-47.385 ; 96.511,-49.671 97.273,-47.385
  lines w0.3: 87.842,-57.796 90.178,-57.796
  text "1" at -39.422,127.167 h1.85
  text "2" at 7.758,127.167 h1.85
  text "3" at 57.758,127.167 h1.85
  text "4" at 107.758,127.167 h1.85
  text "5" at 157.758,127.167 h1.85
  text "6" at 204.718,127.167 h1.85
  text "4" at -58.592,103.909 h1.85
  text "4" at 223.458,103.909 h1.85
  text "3" at -58.592,55.459 h1.85
  text "3" at 223.458,55.459 h1.85
  text "2" at -58.592,5.667 h1.85
  text "2" at 223.458,5.667 h1.85
  text "Polygone CAO" at 155.358,-37.733 h2
  text "BUGNAND S." at 174.358,-37.733 h2
  text "09-07-2018" at 191.158,-37.733 h2
  text "NAPOLEONI J." at 205.358,-37.733 h2
  text "Revision" at 60.358,-41.733 h2
  text "DESCRIPTION" at 70.858,-41.733 h2
  text "COMPAGNY" at 156.058,-41.733 h2
  text "PCB DESIGNER" at 173.358,-41.733 h2
  text "DATE" at 193.258,-41.733 h2
  text "CHECKED BY" at 206.358,-41.733 h2
  text "1" at -58.592,-43.933 h1.85
  text "1" at 223.458,-43.933 h1.85
  text "TITLE" at 113.458,-45.733 h2
  text "Carte MB1378C" at 121.358,-48.733 h5
  text "LAYER" at 143.358,-53.633 h2
  text "REF." at 113.458,-53.733 h2
  text "GERBER" at 207.358,-53.733 h2
  text "AF1806-020" at 121.358,-57.733 h3
  text "Ce document est la propriété de STMICROELECTRONICS et ne peut être reproduit ou transmis sans son autorisation écrite." at 59.258,-61.633 h2.4
  text "A4" at 203.058,-63.733 h4.5
  text "/14" at 214.708,-63.733 h4.5
  text "This document is the property of STMICROELECTRONICS and shall not be reproduced nor transmitted without written approval." at 59.258,-64.033 h2.4
  text "1" at -39.472,-67.833 h1.85
  text "2" at 7.708,-67.833 h1.85
  text "3" at 57.708,-67.833 h1.85
  text "4" at 107.708,-67.833 h1.85
  text "5" at 157.708,-67.833 h1.85
  text "6" at 204.668,-67.833 h1.85
M21-Bottom Title Box:
  circle w0.254: c68.483,-56.907 r1.3
  region: 82.961,-58 93.717,-58 92.723,-55.507 84.866,-55.507 84.417,-54.748 82.208,-57.296
  region: 68.957,-49.671 84.485,-49.671 85.179,-51.446 86.39,-52.671 87.787,-50.811 87.787,-49.16 86.644,-47.763 85.208,-47.385 68.957,-47.385
  lines w0.2: -60.642,-19.733 -55.642,-19.733 ; -55.641,-59.733 107.358,-59.733 ; -55.642,-50.733 54.308,-50.733 ; -55.641,-42.733 107.358,-42.733 ; -55.641,-39.276 107.358,-39.276 ; -55.641,-34.733 107.358,-34.733 107.358,-64.733 ; -55.642,5.267 -55.642,-64.733 ; -43.542,-64.733 -43.542,-59.733 ; -37.642,-42.647 -37.642,-34.733 ; -35.642,-64.733 -35.642,-59.733 ; -22.642,-42.647 -22.642,-34.733 ; -17.142,-69.733 -17.142,-64.733 ; -17.142,125.267 -17.142,130.267 ; -5.642,-42.733 -5.642,-34.733 ; 14.358,-42.647 14.358,-34.733 ; 24.358,-59.733 24.358,-50.733 ; 32.858,-69.733 32.858,-64.733 ; 32.858,125.267 32.858,130.267 ; 54.358,-59.733 54.358,-42.733 ; 82.858,-69.733 82.858,-64.733 ; 82.858,120.267 82.858,130.267 ; 132.858,-69.733 132.858,-64.733 ; 132.858,125.267 132.858,130.267 ; 182.858,-69.733 182.858,-64.733 ; 182.858,125.267 182.858,130.267 ; 216.358,30.267 226.358,30.267 ; 221.358,-19.733 226.358,-19.733 ; 221.358,80.267 226.358,80.267 ; -55.642,-64.733 221.358,-64.733 221.358,125.267 -55.642,125.267 -55.642,-64.733 ; -60.642,-69.733 226.358,-69.733 226.358,130.267 -60.642,130.267 -60.642,-69.733 ; -60.642,30.267 -50.642,30.267 -60.642,30.267 ; -60.642,80.267 -55.642,80.267 -60.642,80.267
  lines w0.254: 68.444,-47.385 69.206,-49.671 ; 68.698,-47.385 69.46,-49.671 ; 68.864,-47.382 69.626,-49.668 ; 68.952,-49.671 68.19,-47.385 84.954,-47.385 cw(c85.194,-50.025) 86.998,-51.969 83.931,-55.507 92.723,-55.507 ; 68.957,-49.671 72.65,-49.671 ; 71.595,-56.283 67.296,-45.506 86.746,-45.506 ; 71.596,-56.285 ccw(c74.145,-55.266) 74.394,-58 93.717,-58 89.37,-47.105 ; 72.65,-49.417 75.539,-57.796 ; 72.878,-49.425 75.748,-57.746 ; 73.132,-49.425 76.002,-57.746 ; 73.386,-49.425 76.256,-57.746 ; 73.64,-49.425 76.51,-57.746 ; 73.894,-49.425 76.764,-57.746 ; 74.148,-49.425 77.018,-57.746 ; 74.286,-49.671 87.279,-49.671 ; 74.402,-49.425 77.272,-57.746 ; 74.656,-49.425 77.526,-57.746 ; 74.783,-49.425 77.653,-57.746 ; 74.986,-49.417 77.875,-57.796 ; 81.31,-55.637 86.615,-49.516 ; 81.31,-55.256 86.615,-49.135 ; 81.437,-56.018 86.742,-49.897 ; 81.437,-55.764 86.742,-49.643 ; 81.437,-54.875 86.742,-48.754 ; 81.491,-56.209 86.742,-50.151 ; 81.509,-54.446 86.814,-48.325 ; 81.564,-56.399 86.869,-50.278 ; 81.691,-56.526 86.996,-50.405 ; 81.818,-56.653 87.123,-50.532 ; 81.945,-56.78 87.25,-50.659 ; 82.072,-57.161 87.377,-51.04 ; 82.072,-56.907 87.377,-50.786 ; 82.208,-57.296 87.631,-51.04 ; 83.219,-57.908 cw(c83.952,-55.359) 82.148,-53.415 84.513,-50.687 ccw(c84.182,-50.224) 84.156,-49.657 ; 84.84,-54.528 ccw(c85.138,-54.985) 85.243,-55.521 ; 86.747,-45.505 cw(c86.983,-48.108) 89.41,-47.137
  lines w0.3: 75.539,-57.796 77.875,-57.796
  text "6" at -39.002,127.167 h1.85
  text "5" at 7.958,127.167 h1.85
  text "4" at 57.958,127.167 h1.85
  text "3" at 107.958,127.167 h1.85
  text "2" at 157.958,127.167 h1.85
  text "1" at 205.138,127.167 h1.85
  text "4" at -57.742,103.909 h1.85
  text "4" at 224.308,103.909 h1.85
  text "3" at -57.742,55.459 h1.85
  text "3" at 224.308,55.459 h1.85
  text "2" at -57.742,5.667 h1.85
  text "2" at 224.308,5.667 h1.85
  text "NAPOLEONI J." at -40.642,-37.733 h2
  text "09-07-2018" at -25.442,-37.733 h2
  text "BUGNAND S." at -8.642,-37.733 h2
  text "Polygone CAO" at 10.358,-37.733 h2
  text "CHECKED BY" at -40.642,-41.733 h2
  text "DATE" at -27.542,-41.733 h2
  text "PCB DESIGNER" at -7.642,-41.733 h2
  text "COMPAGNY" at 9.658,-41.733 h2
  text "DESCRIPTION" at 94.858,-41.733 h2
  text "Revision" at 105.358,-41.733 h2
  text "1" at -57.742,-43.933 h1.85
  text "1" at 224.308,-43.933 h1.85
  text "TITLE" at 52.258,-45.733 h2
  text "Carte MB1378C" at 44.358,-48.733 h5
  text "LAYER" at 22.358,-53.633 h2
  text "GERBER" at -41.642,-53.733 h2
  text "REF." at 52.258,-53.733 h2
  text "AF1806-020" at 44.358,-57.733 h3
  text "Ce document est la propriété de STMICROELECTRONICS et ne peut être reproduit ou transmis sans son autorisation écrite." at 106.458,-61.633 h2.4
  text "/14" at -48.992,-63.733 h4.5
  text "A4" at -37.342,-63.733 h4.5
  text "This document is the property of STMICROELECTRONICS and shall not be reproduced nor transmitted without written approval." at 106.458,-64.033 h2.4
  text "6" at -38.952,-67.833 h1.85
  text "5" at 8.008,-67.833 h1.85
  text "4" at 58.008,-67.833 h1.85
  text "3" at 108.008,-67.833 h1.85
  text "2" at 158.008,-67.833 h1.85
  text "1" at 205.188,-67.833 h1.85
Mechanical 29:
  lines w0.5: 37.685,43.549 48.15,43.549 68.392,43.549 86.582,43.549 101.522,43.549 115.35,43.549 ; 37.685,48.549 48.15,48.549 68.392,48.549 86.582,48.549 101.522,48.549 115.35,48.549 ; 37.685,53.549 48.15,53.549 68.392,53.549 86.582,53.549 101.522,53.549 115.35,53.549 ; 37.685,58.549 48.15,58.549 68.392,58.549 86.582,58.549 101.522,58.549 115.35,58.549 ; 37.685,63.549 48.15,63.549 68.392,63.549 86.582,63.549 101.522,63.549 115.35,63.549 ; 37.685,68.549 48.15,68.549 68.392,68.549 86.582,68.549 101.522,68.549 115.35,68.549 ; 37.685,73.549 48.15,73.549 68.392,73.549 86.582,73.549 101.522,73.549 115.35,73.549 ; 37.685,78.549 48.15,78.549 68.392,78.549 86.582,78.549 101.522,78.549 115.35,78.549 ; 37.685,83.549 48.15,83.549 68.392,83.549 86.582,83.549 101.522,83.549 115.35,83.549 ; 37.685,88.549 48.15,88.549 68.392,88.549 86.582,88.549 101.522,88.549 115.35,88.549 ; 37.685,93.549 115.35,93.549 ; 48.15,98.549 48.15,38.549 ; 68.392,98.549 68.392,38.549 ; 86.582,98.549 86.582,38.549 ; 101.522,98.549 101.522,38.549 ; 48.15,38.549 37.685,38.549 37.685,98.549 115.35,98.549 115.35,38.549 101.522,38.549 ; 48.15,38.549 68.392,38.549 ; 68.392,38.549 86.582,38.549 ; 86.582,38.549 101.522,38.549
  text "6" at 67.768,113.924 h2.54
  text "2" at 2.743,110.952 h2.54
  text "L2-GND" at 8.743,110.945 h2.54
  text "EDGE COUPLED" at 30.743,110.945 h2.54
  text "3" at 2.718,107.98 h2.54
  text "L3" at 8.718,107.973 h2.54
  text "4" at 2.743,105.199 h2.54
  text "Bottom Layer" at 8.743,105.199 h2.54
  text "EDGE COUPLED" at 30.743,105.199 h2.54
  text "6" at 67.743,105.199 h2.54
  text "90 Ohms" at 79.743,105.199 h2.54
  text "10" at 96.743,105.199 h2.54
  text "3" at 109.793,105.199 h2.54
  text "6" at 53.843,105.099 h2.54
  text "Layer" at 40.185,94.799 h2.5
  text "Name" at 50.65,94.799 h2.5
  text "Material" at 70.892,94.799 h2.5
  text "Thickness" at 89.082,94.799 h2.5
  text "Constant" at 104.022,94.799 h2.5
  text "1" at 40.185,89.799 h2.5
  text "Top Overlay" at 50.65,89.799 h2.5
  text "2" at 40.185,84.799 h2.5
  text "Top Solder" at 50.65,84.799 h2.5
  text "Solder Resist" at 70.892,84.799 h2.5
  text "0.59mil" at 89.082,84.799 h2.5
  text "3.5" at 104.022,84.799 h2.5
  text "3" at 40.185,79.799 h2.5
  text "Top Layer" at 50.65,79.799 h2.5
  text "Copper" at 70.892,79.799 h2.5
  text "1.38mil" at 89.082,79.799 h2.5
  text "4" at 40.185,74.799 h2.5
  text "Dielectric 1" at 50.65,74.799 h2.5
  text "FR-4" at 70.892,74.799 h2.5
  text "4.35mil" at 89.082,74.799 h2.5
  text "3.95" at 104.022,74.799 h2.5
  text "5" at 40.185,69.799 h2.5
  text "L2-GND" at 50.65,69.799 h2.5
  text "Copper" at 70.892,69.799 h2.5
  text "1.38mil" at 89.082,69.799 h2.5
  text "6" at 40.185,64.799 h2.5
  text "Dielectric 2" at 50.65,64.799 h2.5
  text "16.14mil" at 89.082,64.799 h2.5
  text "3.95" at 104.022,64.799 h2.5
  text "7" at 40.185,59.799 h2.5
  text "L3" at 50.65,59.799 h2.5
  text "Copper" at 70.892,59.799 h2.5
  text "1.38mil" at 89.082,59.799 h2.5
  text "8" at 40.185,54.799 h2.5
  text "Dielectric 3" at 50.65,54.799 h2.5
  text "4.35mil" at 89.082,54.799 h2.5
  text "3.95" at 104.022,54.799 h2.5
  text "9" at 40.185,49.799 h2.5
  text "Bottom Layer" at 50.65,49.799 h2.5
  text "Copper" at 70.892,49.799 h2.5
  text "1.38mil" at 89.082,49.799 h2.5
  text "10" at 40.185,44.799 h2.5
  text "Bottom Solder" at 50.65,44.799 h2.5
  text "Solder Resist" at 70.892,44.799 h2.5
  text "0.59mil" at 89.082,44.799 h2.5
  text "3.5" at 104.022,44.799 h2.5
  text "11" at 40.185,39.799 h2.5
  text "Bottom Overlay" at 50.65,39.799 h2.5
Mechanical 30:
  text "X" at 154.508,110.367 h3.3
  text "X" at 192.408,110.367 h3.3
  text "X" at 150.858,107.367 h3.3
  text "X" at 179.358,86.367 h3.3
  text "X" at 166.867,45.812 h3.3
  text "X" at 192.261,11.367 h3
  text "X" at 167.308,-6.633 h3.3
  text "X" at 142.261,-23.137 h3.3

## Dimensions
26.517,71.999 to 0,0 on M2-Board Dimensions
-26.107,17.649 to 0,0 on M2-Board Dimensions
28.109,50.399 to -26.107,38.049 on M2-Board Dimensions
26.163,71.999 to -0.531,-8.099 on M2-Board Dimensions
